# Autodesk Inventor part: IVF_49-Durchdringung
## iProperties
Created: 2009-05
Part Number: IVF_49-Durchdringung
Material: 1.4301 X5CrNi10-10 A2
Document SubType Name: Blech
Designer: Gawin
Density: 7.86 g/cm^3
Author: Gawin
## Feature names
1. Umdrehung1 [Revolution]
2. Extrusion1
3. Extrusion3
